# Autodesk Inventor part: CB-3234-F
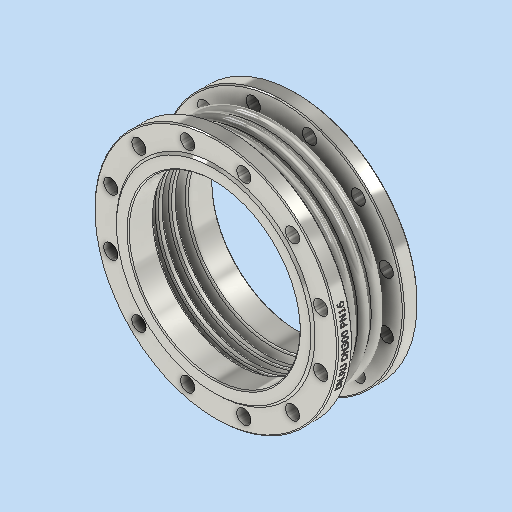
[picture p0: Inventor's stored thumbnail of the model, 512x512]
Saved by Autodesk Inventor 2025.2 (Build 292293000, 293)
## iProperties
Company: DN.RU
Created: 2026-04
Part Number: CB-3234-F
Material: Типовые
Document SubType Name: Modeling
Designer: DN.RU
Density: 7.04566 g/cm^3
Appearance: По умолчанию
Description: D140-02121
Mass: 40000 g
Surface Area: 12949 cm^2
Volume: 5677.25 cm^3
Author: DN.RU
Title: Компенсатор сильфонный осевой DN.ru Ду300 Ру16
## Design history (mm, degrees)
sketch "Эскиз1"
  geometry: L1 (0, 0)-(0, -80); L2 (171.5, -80)-(171.5, 0); L3 (171.5, 0)-(0, 0); L4 (171.5, 0)-(171.5, 0); L5 (141.5, 0)-(201.5, 0); L6 (141.5, -9)-(201.5, -9); L7 (201.5, 9)-(141.5, 9); L8 (201.5, -6)-(141.5, -6); L9 (141.5, 6)-(201.5, 6); L10 (201.5, -16)-(141.5, -16); L11 (141.5, -19)-(201.5, -19); L12 (141.5, -25)-(201.5, -25); L13 (141.5, -34)-(201.5, -34); L14 (201.5, -31)-(141.5, -31); L15 (0, -80)-(171.5, -80); L16 (171.5, -80)-(161.5, -80); L17 (161.5, -80)-(161.5, -31); L18 (171.5, -19)-(168.5, -19); L19 (168.5, -19)-(168.5, -6); L20 (171.5, 6)-(168.5, 6); L21 (168.5, 6)-(168.5, 0); L22 (0, -80)-(0, -48); L23 (0, -48)-(230, -48); L24 (230, -48)-(230, -80); L25 (230, -80)-(0, -80); L26 (171.5, -48)-(171.5, -66); L27 (171.5, -66)-(176.5, -66); L28 (176.5, -66)-(176.5, -48); L29 (176.5, -48)-(171.5, -48); L30 (171.5, 0)-(210.5, 0); A1 r 9 centre (141.5, 0) between (141.5, 9) and (141.5, -9); A2 r 9 centre (201.5, 0) between (201.5, -9) and (201.5, 9); A3 r 6 centre (141.5, 0) between (141.5, 6) and (141.5, -6); A4 r 6 centre (201.5, 0) between (201.5, -6) and (201.5, 6); A5 r 6 centre (141.5, -25) between (141.5, -19) and (141.5, -31); A6 r 9 centre (141.5, -25) between (141.5, -16) and (141.5, -34); A7 r 6 centre (201.5, -25) between (201.5, -31) and (201.5, -19); A8 r 9 centre (201.5, -25) between (201.5, -34) and (201.5, -16); 20 further points
  constraints: 64 end point, 17 point on circle, 14 point on line, 8 centre point, 7 parallel, 5 perpendicular, 4 tangent, 3 midpoint, 2 vertical, 1 horizontal, 25 other
  dimensions: "d0" = 80 distance of L1.start L1.end; "d3" = 0 distance of L2.end L4.end; "d4" = 30 distance of L4.end L5.end; "d5" = 18 diameter of A2; "d6" = 3 distance between parallel lines of L6 L8; "d9" = 25 distance of L4.end point (171.5, -25); "d18" = 3 distance of L18.start L18.end; "d19" = 3 distance of L20.start L20.end; "d27" = 161.5 distance between parallel lines of L1 L17; "d28" = 10 distance between parallel lines of L2 L17; "d29" = 32 distance of L1.end L22.end; "d30" = 230 distance of L22.end L23.end; "d31" = 18 distance of L26.start L26.end; "d32" = 5 distance of L27.end L26.end
revolve "Вращение1" sketch "Эскиз1" stored, may be unused: angle "d20" = 360 deg
sketch "Эскиз3" dims "d33" = 410
  geometry: L1 (0, 0)-(74.331, 19.917); L2 (0, 0)-(76.954, 0); C1 r 13.5 at (198.015, 53.058); C2 r 13.5 at (144.957, 144.957); C3 r 13.5 at (53.058, 198.015); C4 r 13.5 at (-53.058, 198.015); C5 r 161.5 at (0, 0) reference; C6 r 187.5 at (0, 0); C7 r 230 at (0, 0) reference; C8 r 13.5 at (-144.957, 144.957); C9 r 13.5 at (-198.015, 53.058); C10 r 13.5 at (-198.015, -53.058); C11 r 13.5 at (-144.957, -144.957); C12 r 13.5 at (-53.058, -198.015); C13 r 13.5 at (53.058, -198.015); C14 r 13.5 at (144.957, -144.957); C15 r 13.5 at (198.015, -53.058); 1 further point
  constraints: 13 centre point, 4 end point, 2 coincident, 1 equal length, 1 horizontal, 1 point on line, 28 other
  dimensions: "d34" = 15 deg angle of L2 L1; "d35" = 27 diameter of C1; "d38" = 360 deg dimension on point (0, 0) C1.centre (derived); "d40" = 375 diameter of C6
  node "Эскиз — круговой массив1" dims "d38" = 360 deg (derived)
extrude "Выдавливание1" cut sketch "Эскиз3" stored distance "d41" = 10; taper "d42" = 0 deg
extrude "Выдавливание2" cut sketch "Эскиз3" distance "d43" = 4; taper "d44" = 0 deg
chamfer "Фаска2" distance "d45" = 4; stored, may be unused: second distance "d46" = 2, angle "d47" = 45 deg
chamfer "Фаска3" distance "d48" = 2; stored, may be unused: second distance "d49" = 2, angle "d50" = 45 deg
mirror "Зеркальное отражение2"
fillet "Сопряжение2" dims "d51" = 3
node "РабПлоскость2"
sketch "Эскиз4"
  geometry: L1 (-79.676, 4.102)-(96.959, 4.102); L2 (96.959, 4.102)-(96.959, -37.018); L3 (96.959, -37.018)-(-79.676, -37.018); L4 (-79.676, -37.018)-(-79.676, 4.102); 1 further point
  constraints: 2 other
feature "Рельеф2" sketch "Эскиз4" dims "d52" = 0.1, "d53" = 0
feature "ɓ耀ɕ耀ɗ耀ə耀ɛ耀ɝ耀ɟ耀ɡ耀" dims "d0" = 80, "d3" = 0, "d4" = 30, "d5" = 18, "d6" = 3, "d7" = 20, "d9" = 25, "d10" = 10, "d12" = 10, "d18" = 3, "d19" = 3, "d20" = 360 deg, "d27" = 161.5, "d28" = 10, "d29" = 32, "d30" = 230, "d31" = 18, "d32" = 5, "d33" = 410, "d34" = 15 deg, "d35" = 27, "d36" = 120, "d38" = 360 deg (derived), "d40" = 375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
node "Твердое тело1"
node "Эскиз — прямоугольный массив1" dims "d9" = 25, "d12" = 10
